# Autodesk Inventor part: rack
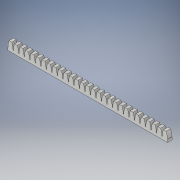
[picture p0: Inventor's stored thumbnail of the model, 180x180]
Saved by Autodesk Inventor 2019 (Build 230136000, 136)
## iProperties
Created: 2019-11
Part Number: rack
Material: Generic
Document SubType Name: Sheet Metal
Designer: PRADYUMNA
Density: 1 g/cm^3
Sheet Metal Rule: Default_mm
Appearance: Default
Author: PRADYUMNA
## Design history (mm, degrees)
sketch "Sketch1"
  geometry: L1 (29.36, 3.84)-(-543.64, 3.84); L2 (-543.64, 3.84)-(-543.64, -12.16); L3 (-543.64, -12.16)-(29.36, -12.16); L4 (29.36, -12.16)-(29.36, 3.84); 1 further point
  constraints: 8 end point, 2 parallel, 1 horizontal, 1 perpendicular
  dimensions: "d0" = 16 distance of L3.end L1.start; "d1" = 573 distance of L2.end L3.end
extrude "Extrusion1" new body sketch "Sketch1" distance "d2" = 10; taper "d3" = 0 deg
sketch "Sketch2"
  geometry: L1 (0, 10)-(573, 10) reference; L2 (3.896, 32.795)-(13.927, 32.795); A1 r 65.103 centre (65.1, 10.603) between (3.896, 32.795) and (0, 10); A2 r 64.28 centre (-45.903, 9.293) between (18.373, 10) and (13.927, 32.795); 1 further point
  constraints: 4 point on circle, 2 centre point, 2 end point, 1 horizontal, 1 point on line
extrude "Extrusion2" join sketch "Sketch2" distance "d4" = 16; taper "d5" = 0 deg
sketch "Sketch3"
  geometry: L1 (0, 0)-(0, 10) reference; L2 (0, 0)-(16, 0) reference; L3 (0, 10)-(16, 10); L4 (16, 10)-(16, 0); L5 (16, 0)-(0, 0); L6 (0, 0)-(0, 10); 1 further point
  constraints: 8 end point, 2 parallel, 1 horizontal, 1 perpendicular
extrude "Extrusion3" join sketch "Sketch3" distance "d9" = 6; taper "d10" = 0 deg
body "Solid1"
pattern_linear "Rectangular Pattern1" dims "d8" = 20
other parameters: "Thickness" = 0.5, "BendRadius" = 0.5 (= Thickness), "BendReliefWidth" = 0.5 (= Thickness), "BendReliefDepth" = 0.25 (= 0.5 x Thickness), "CornerReliefSize" = 2 (= 4 x Thickness), "SeamGap" = 0.01, "MinimumRemnant" = 1 (= 2 x Thickness), "TransitionRadius" = 0.5 (= BendRadius), "JacobiRadiusSize" = 0.5 (= BendRadius), "GapSize" = 0.5 (= Thickness)
